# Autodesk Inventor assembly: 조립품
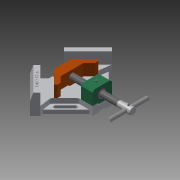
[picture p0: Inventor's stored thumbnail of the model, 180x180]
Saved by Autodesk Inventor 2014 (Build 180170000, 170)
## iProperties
Created: 2020-05
Part Number: 조립품
Document SubType Name: Assembly
Designer: kh
Author: kh
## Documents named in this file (11)
- C:\Users\kh\Desktop\700506V1031\조립품.iam
- C:\Users\kh\Desktop\700506V1031\베이스.ipt
- C:\Users\kh\Desktop\700506V1031\리드스크류.ipt
- C:\Users\kh\Desktop\700506V1031\멈춤나사 M4x5.ipt
- C:\Users\kh\Desktop\700506V1031\멈춤나사 M4x10.ipt
- C:\Users\kh\Desktop\700506V1031\볼트 M4x16.ipt
- C:\Users\kh\Desktop\700506V1031\부시.ipt
- C:\Users\kh\Desktop\700506V1031\서포트.ipt
- C:\Users\kh\Desktop\700506V1031\조.ipt
- C:\Users\kh\Desktop\700506V1031\평행 핀 2.5x24.ipt
- C:\Users\kh\Desktop\700506V1031\핸들.ipt
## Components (1 placed, 1 different names)
1. 핸들:1 — Mate:9, Mate:11, Mate:12, Angle:1
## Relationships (4: Mate 3, Angle 1)
- Mate:9: 핸들:1
- Mate:11: 핸들:1
- Mate:12: 핸들:1
- Angle:1: 핸들:1
